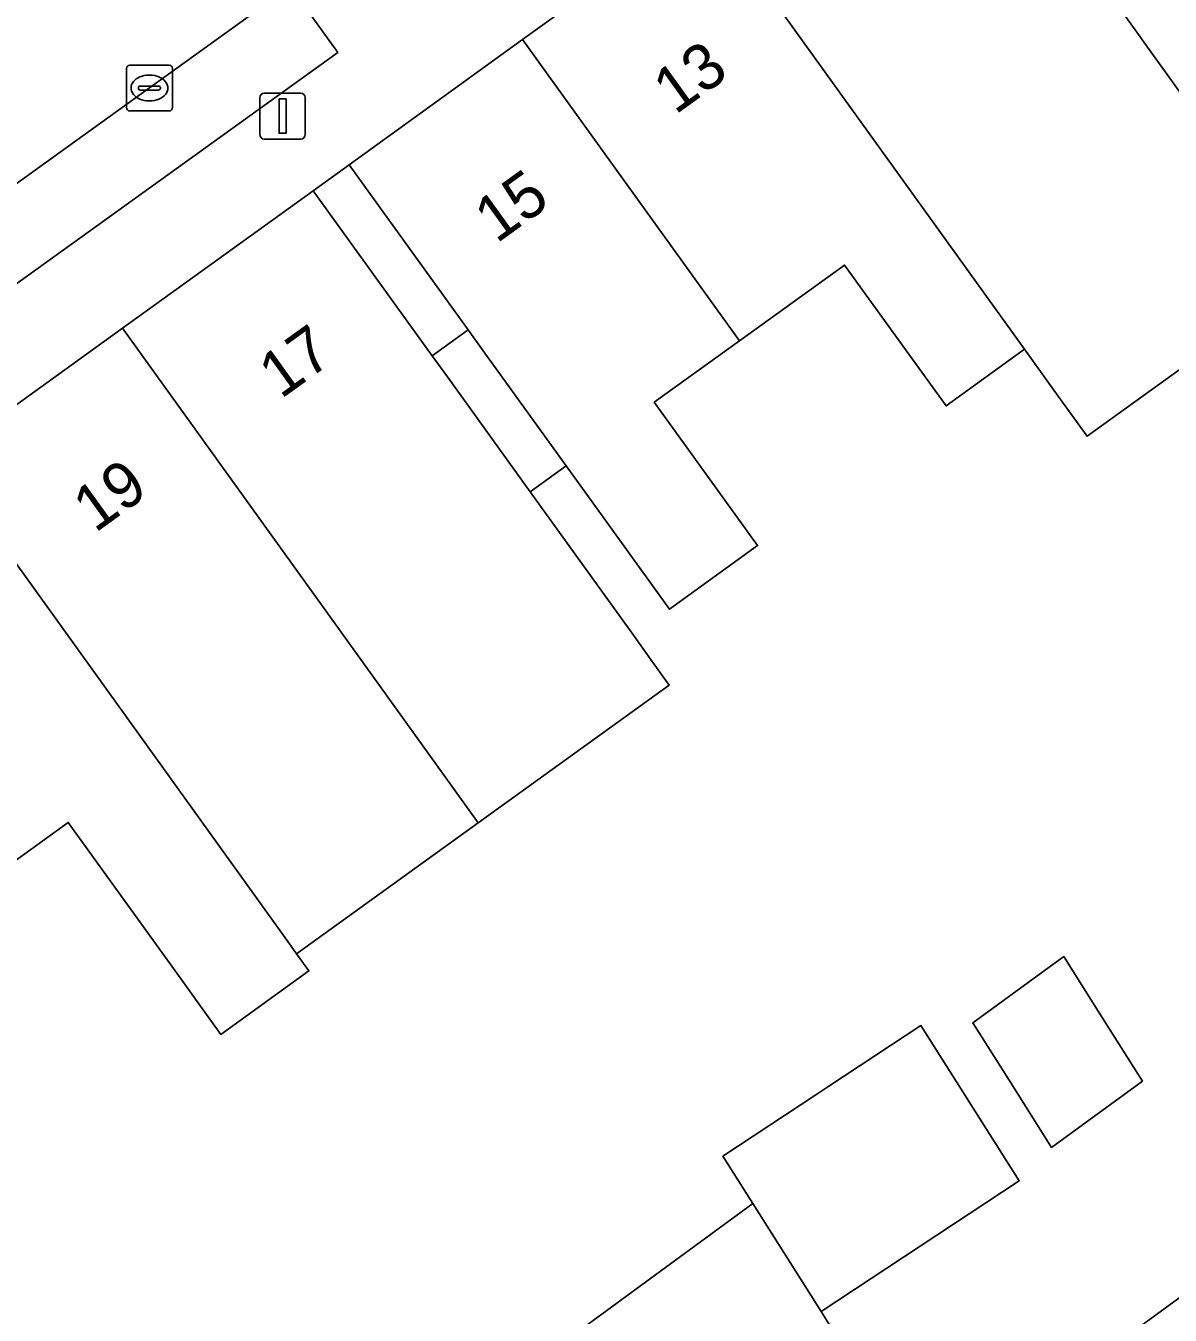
# Model space of a CAD drawing. Extents: x 161881 to 162523, y 381678 to 382381.
# Drawn here: x 162267.3 to 162292.22, y 381897.16 to 381925.24 of the extents above; entities that cross this region are included whole.
import ezdxf

# ---------------------------------------------------------------- set-up
doc = ezdxf.new("R2010")
doc.units = 0
for name, color, linetype in [('IMGEO_Erf', 7, 'Continuous'), ('IMGEO_Kolk', 7, 'Continuous'), ('IMGEO_Lichtmast', 7, 'Continuous'), ('IMGEO_Pand', 7, 'Continuous'), ('IMGEO_Pand_nummerreeks', 7, 'Continuous'), ('IMGEO_Pand_overbouw', 7, 'Continuous'), ('IMGEO_Parkeervlak_open', 7, 'Continuous'), ('IMGEO_Rijbaan_lokaal_open', 7, 'Continuous'), ('IMGEO_Voetpad_open', 7, 'Continuous')]:
    doc.layers.add(name, color=color, linetype=linetype)

msp = doc.modelspace()

# ---------------------------------------------------------------- linework, layer by layer
at = {"layer": 'IMGEO_Erf'}
for points in [[(162294.146, 381918.993), (162290.41, 381916.301), (162290.273, 381916.491), (162289.685, 381917.308), (162289.047, 381918.195), (162287.337, 381916.962), (162285.128, 381920.028), (162282.836, 381918.376), (162280.984, 381917.041), (162283.233, 381913.92), (162281.311, 381912.535), (162279.063, 381915.656), (162277.259, 381918.159), (162276.929, 381918.617), (162274.337, 381922.215), (162273.553, 381921.649), (162276.146, 381918.052), (162276.476, 381917.593), (162278.279, 381915.091), (162280.527, 381911.97), (162280.901, 381911.451), (162281.31, 381910.883), (162277.151, 381907.885), (162273.193, 381905.032), (162273.461, 381904.661), (162271.545, 381903.279), (162270.511, 381904.714), (162268.22, 381907.894), (162266.116, 381906.378)], [(162275.507, 381885.197), (162313.123, 381912.663)]]:
    msp.add_lwpolyline(points, dxfattribs=at)
for points in [[(162287.923, 381903.531), (162289.899, 381904.973), (162290.688, 381903.724), (162291.613, 381902.261), (162289.637, 381900.818), (162288.713, 381902.281)], [(162278.151, 381891.503), (162277.827, 381892.015), (162277.662, 381892.277), (162276.229, 381894.543), (162279.326, 381896.811), (162283.128, 381899.595), (162282.478, 381900.624), (162284.502, 381901.961), (162284.785, 381902.148), (162286.788, 381903.471), (162286.974, 381903.176), (162288.926, 381900.089), (162284.616, 381897.241), (162285.049, 381896.555), (162281.247, 381893.771)]]:
    msp.add_lwpolyline(points, close=True, dxfattribs=at)
at = {"layer": 'IMGEO_Kolk'}
for p, q in [((162269.488, 381923.458), (162269.488, 381924.31)), ((162269.563, 381924.384), (162270.415, 381924.384)), ((162270.489, 381924.31), (162270.489, 381923.458)), ((162269.976, 381924.164), (162270.001, 381924.164)), ((162269.747, 381923.878), (162269.747, 381923.89)), ((162270.185, 381923.841), (162269.787, 381923.841)), ((162269.79, 381923.927), (162270.188, 381923.927)), ((162270.231, 381923.89), (162270.231, 381923.878)), ((162269.999, 381923.604), (162269.974, 381923.604)), ((162270.415, 381923.384), (162269.563, 381923.384))]:
    msp.add_line(p, q, dxfattribs=at)
for points in [[(162269.488, 381923.458), (162269.488, 381924.31)], [(162269.563, 381924.384), (162270.415, 381924.384)], [(162270.489, 381924.31), (162270.489, 381923.458)], [(162270.415, 381923.384), (162269.563, 381923.384)]]:
    msp.add_lwpolyline(points, dxfattribs=at)
for centre, radius, start, end in [((162269.565, 381924.308), 0.0765, 91.552, 178.448), ((162269.565, 381924.308), 0.0765, 91.552, 178.448), ((162270.413, 381924.308), 0.0765, 1.552, 88.448), ((162270.413, 381924.308), 0.0765, 1.552, 88.448), ((162269.787, 381923.887), 0.0403, 85.8775, 175.7526), ((162269.784, 381923.877), 0.0366, 178.938, 274.7102), ((162270.188, 381923.884), 0.043, 264.8664, 352.4533), ((162270.192, 381923.889), 0.0386, 1.7309, 96.639), ((162269.565, 381923.46), 0.0765, 181.552, 268.448), ((162269.565, 381923.46), 0.0765, 181.552, 268.448), ((162270.413, 381923.46), 0.0765, 271.552, 358.448), ((162270.413, 381923.46), 0.0765, 271.552, 358.448)]:
    msp.add_arc(centre, radius, start, end, dxfattribs=at)
for centre, major_axis, ratio, start_param, end_param in [((162269.975, 381923.884), (-0.387, 0.002), 0.722429, 4.712389, 7.853982), ((162270, 381923.884), (-0.39, 0.002), 0.717154, 1.570796, 4.712389)]:
    msp.add_ellipse(centre, major_axis=major_axis, ratio=ratio, start_param=start_param, end_param=end_param, dxfattribs=at)
at = {"layer": 'IMGEO_Lichtmast'}
for p, q in [((162272.393, 381922.873), (162272.393, 381923.673)), ((162272.393, 381923.673), (162272.393, 381922.873)), ((162272.493, 381923.773), (162273.283, 381923.773)), ((162273.283, 381923.773), (162272.493, 381923.773)), ((162273.383, 381923.673), (162273.383, 381922.873)), ((162273.383, 381922.873), (162273.383, 381923.673)), ((162273.283, 381922.773), (162272.493, 381922.773)), ((162272.493, 381922.773), (162273.283, 381922.773))]:
    msp.add_line(p, q, dxfattribs=at)
msp.add_lwpolyline([(162272.813, 381923.648), (162272.963, 381923.648), (162272.963, 381922.898), (162272.813, 381922.898), (162272.813, 381923.648)], dxfattribs=at)
for centre, start, end in [((162272.493, 381923.673), 90, 180), ((162272.493, 381923.673), 90, 180), ((162273.283, 381923.673), 0, 90), ((162273.283, 381923.673), 360, 90), ((162272.493, 381922.873), 180, 270), ((162272.493, 381922.873), 180, 270), ((162273.283, 381922.873), 270, 0), ((162273.283, 381922.873), 270, 0)]:
    msp.add_arc(centre, 0.1, start, end, dxfattribs=at)
at = {"layer": 'IMGEO_Pand'}
for points in [[(162292.689, 381935.439), (162287, 381931.34), (162291.49, 381925.097), (162291.687, 381924.824), (162293.546, 381922.239), (162294.228, 381921.291), (162295.289, 381919.817), (162298.468, 381922.107), (162300.987, 381923.922)], [(162287, 381931.34), (162282.121, 381927.824), (162289.047, 381918.195), (162289.685, 381917.308), (162290.273, 381916.491), (162290.41, 381916.301), (162294.146, 381918.993), (162295.289, 381919.817), (162294.228, 381921.291), (162293.546, 381922.239), (162291.687, 381924.824), (162291.49, 381925.097)], [(162282.836, 381918.376), (162285.128, 381920.028), (162287.337, 381916.962), (162289.047, 381918.195), (162282.121, 381927.824), (162278.116, 381924.938)], [(162278.116, 381924.938), (162274.337, 381922.215), (162276.929, 381918.617), (162277.259, 381918.159), (162279.063, 381915.656), (162281.311, 381912.535), (162283.233, 381913.92), (162280.984, 381917.041), (162282.836, 381918.376)], [(162276.476, 381917.593), (162276.146, 381918.052), (162273.553, 381921.649), (162269.402, 381918.658), (162274.13, 381912.085), (162277.151, 381907.885), (162281.31, 381910.883), (162280.901, 381911.451), (162280.527, 381911.97), (162278.279, 381915.091)], [(162269.402, 381918.658), (162265.442, 381915.805), (162272.428, 381906.096), (162273.073, 381905.2), (162273.193, 381905.032), (162277.151, 381907.885), (162274.13, 381912.085)], [(162265.442, 381915.805), (162261.414, 381912.903), (162264.337, 381908.846), (162266.116, 381906.378), (162268.22, 381907.894), (162270.511, 381904.714), (162271.545, 381903.279), (162273.461, 381904.661), (162273.193, 381905.032), (162273.073, 381905.2), (162272.428, 381906.096)], [(162315.068, 381901.394), (162318.477, 381896.725), (162315.645, 381894.334), (162320.508, 381888.575), (162331.126, 381897.517), (162324.457, 381905.392), (162322.762, 381907.393), (162318.985, 381904.635), (162313.123, 381912.663), (162275.507, 381885.197), (162281.55, 381876.921)], [(162289.637, 381900.818), (162291.613, 381902.261), (162290.688, 381903.724), (162289.899, 381904.973), (162287.923, 381903.531), (162288.713, 381902.281)], [(162283.128, 381899.595), (162284.616, 381897.241), (162288.926, 381900.089), (162286.974, 381903.176), (162286.788, 381903.471), (162284.785, 381902.148), (162284.502, 381901.961), (162282.478, 381900.624)], [(162284.616, 381897.241), (162283.128, 381899.595), (162279.326, 381896.811), (162281.247, 381893.771), (162285.049, 381896.555)]]:
    msp.add_lwpolyline(points, close=True, dxfattribs=at)
at = {"layer": 'IMGEO_Pand_overbouw'}
for points in [[(162276.146, 381918.052), (162276.929, 381918.617), (162274.337, 381922.215), (162273.553, 381921.649)], [(162276.929, 381918.617), (162276.146, 381918.052), (162276.476, 381917.593), (162278.279, 381915.091), (162279.063, 381915.656), (162277.259, 381918.159)]]:
    msp.add_lwpolyline(points, close=True, dxfattribs=at)
at = {"layer": 'IMGEO_Parkeervlak_open'}
msp.add_lwpolyline([(162273.463, 381926.395), (162269.991, 381923.887), (162260.256, 381916.887), (162257.825, 381915.139), (162253.349, 381911.92), (162238.365, 381901.138), (162234.555, 381898.412), (162224.359, 381891.116), (162225.354, 381889.595), (162274.088, 381924.659), (162273.358, 381925.677)], dxfattribs=at)
at = {"layer": 'IMGEO_Rijbaan_lokaal_open'}
msp.add_lwpolyline([(162271.201, 381929.808), (162271.019, 381929.676), (162257.85, 381920.248), (162260.256, 381916.887), (162269.991, 381923.887), (162273.463, 381926.395), (162273.607, 381926.495)], close=True, dxfattribs=at)
at = {"layer": 'IMGEO_Voetpad_open'}
for points in [[(162236.204, 381894.826), (162240.549, 381897.926), (162245.371, 381901.367), (162246.608, 381902.233), (162251.586, 381905.819), (162252.439, 381906.434), (162256.346, 381909.25), (162260.577, 381912.299), (162260.997, 381912.602), (162261.414, 381912.903), (162265.442, 381915.805), (162269.402, 381918.658), (162273.553, 381921.649), (162274.337, 381922.215), (162278.116, 381924.938), (162282.121, 381927.824), (162287, 381931.34), (162292.689, 381935.439)], [(162273.358, 381925.677), (162274.088, 381924.659), (162225.354, 381889.595), (162224.004, 381888.624), (162214.822, 381882.018), (162214.15, 381883.202)]]:
    msp.add_lwpolyline(points, dxfattribs=at)

# ---------------------------------------------------------------- texts
at = {"layer": 'IMGEO_Pand_nummerreeks'}
for s, rotation, p in [('13', 35.7765, (162281.439, 381923.29)), ('15', 35.7755, (162277.547, 381920.486)), ('17', 35.7698, (162272.85, 381917.1)), ('19', 35.7698, (162268.804, 381914.185))]:
    msp.add_text(s, height=1, rotation=rotation, dxfattribs=at).set_placement(p)

doc.saveas('drawing.dxf')
